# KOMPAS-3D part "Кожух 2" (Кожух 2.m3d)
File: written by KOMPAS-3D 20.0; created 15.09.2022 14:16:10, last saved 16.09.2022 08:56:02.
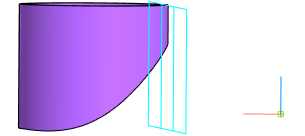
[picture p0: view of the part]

Document properties: Полное имя файла: D:\YAKOVLEV\ПРОЕКТЫ\ДЦ-2. ДП-7 Газопровод Окожушивание\ПРОБА Соединение труб. Окожушивание\ПРОБА 2\Кожух 2.m3d

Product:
- Part/product: Кожух 2
    Материал: Сталь 45  ГОСТ 1050-2013 (density 7810 kg/m3)
    Масса: 2058.57

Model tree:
1. Эскиз:1  (with: Смещенная плоскость:1, Обечайка:1)  (labels: Кожух 2 (вставки))
2. Обечайка:1  (labels: Кожух 1)
     Расстояние 1 = 743.079
3. Сгиб(1) - Обечайка:1
     Радиус сгиба = 610; Коэффициент = 0.5; Величина сгиба = 10; Зазор = 0.01; Угол = 180; Параметр U, % = 11; Длина = 366.31
4. Касательная плоскость:1  (with: Обечайка:1)
5. Разогнуть:1  (with: Обечайка:1)
6. Смещенная плоскость:1  (with: Обечайка:1)
     Расстояние = 0.1
7. Эскиз:3  (with: Обечайка:1)
8. Вырез в листовом теле:3
     Глубина выреза = 100
9. Элемент выдавливания:1
     Расстояние 2 = 20
10. Эскиз:4  (with: Обечайка:1, Вырез в листовом теле:3)
11. Вырез в листовом теле:4
     Глубина выреза = 100
12. Согнуть:1  (with: Обечайка:1)
13. Развертка  (labels: Сталь 45  ГОСТ 1050-2013)

Referenced files in D:\YAKOVLEV\ПРОЕКТЫ\ДЦ-2. ДП-7 Газопровод Окожушивание\ПРОБА Соединение труб. Окожушивание\: Соединение труб. Окожушивание -2.a3d
Referenced files in D:\YAKOVLEV\ПРОЕКТЫ\ДЦ-2. ДП-7 Газопровод Окожушивание\ПРОБА Соединение труб. Окожушивание\ПРОБА 2\: Соединение труб. Окожушивание -2.a3d
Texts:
  Соединение труб. Окожушивание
